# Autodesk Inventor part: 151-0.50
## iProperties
Created: 2007-06
Part Number: 151-0.50
Document SubType Name: Modeling
Designer: btaylor
Density: 1 g/cm^3
Author: btaylor
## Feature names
1. Sweep1
2. Extrusion1
3. Extrusion2
4. Fillet1
5. Fillet2
6. Extrusion3
7. Extrusion4
8. Sweep2
9. Fillet3
10. Fillet4
11. Chamfer1
12. Chamfer2
13. Fillet5
14. Fillet6
